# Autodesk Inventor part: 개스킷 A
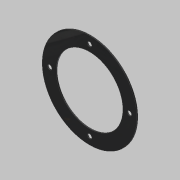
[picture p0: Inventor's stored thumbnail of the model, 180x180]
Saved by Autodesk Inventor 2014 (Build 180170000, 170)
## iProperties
Created: 2019-10
Part Number: 개스킷 A
Material: 고무
Document SubType Name: Modeling
Designer: mduedu
Density: 0.93 g/cm^3
Appearance: Rubber - Black - Version 1.1
Mass: 3.25402 g
Surface Area: 75.6338 cm^2
Volume: 3.49895 cm^3
Author: mduedu
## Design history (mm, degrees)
sketch "스케치1"
  geometry: C1 r 47.5 at (0, 0); C2 r 33.5 at (0, 0); 1 further point
  constraints: 2 centre point, 2 coincident
  dimensions: "d0" = 95 diameter of C1; "d1" = 67 diameter of C2
extrude "돌출1" new body sketch "스케치1" distance "d2" = 1; taper "d3" = 0 deg
sketch "스케치2" dims "d4" = 80
  geometry: C1 r 2.25 at (0, 40); 2 further points
  constraints: 2 vertical alignment, 1 centre point, 1 coincident, 2 other
  dimensions: "d5" = 4.5 diameter of C1
extrude "돌출2" cut sketch "스케치2" stored distance "d6" = 1; taper "d7" = 0 deg
node "솔리드1"
pattern_circular "원형 패턴1" dims angle "d9" = 360 deg
